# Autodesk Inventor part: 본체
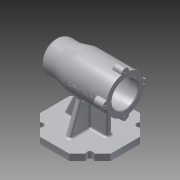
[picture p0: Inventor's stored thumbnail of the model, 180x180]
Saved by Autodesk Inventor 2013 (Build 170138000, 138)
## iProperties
Created: 2019-12
Part Number: 본체
Material: 알루미늄 6061
Document SubType Name: Modeling
Designer: Administrator
Density: 2.71 g/cm^3
Mass: 735.817 g
Surface Area: 721.015 cm^2
Volume: 271.519 cm^3
Author: Administrator
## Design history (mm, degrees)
sketch "스케치1"
  geometry: L1 (-56, 0)-(56, 0); L2 (-56, 0)-(-56, 25); L3 (-56, 25)-(-31, 25); L4 (-31, 25)-(-11, 30); L5 (-11, 30)-(56, 30); L6 (56, 30)-(56, 0); 2 further points
  constraints: 12 end point, 3 perpendicular, 1 coincident, 1 horizontal, 1 midpoint, 1 parallel
  dimensions: "d0" = 25 distance from line of L3.end L2; "d2" = 45 distance from line of L4.end L2; "d3" = 112 distance of L1.start L1.end; "d4" = 50 diameter of L3 L1; "d5" = 60 diameter of L5 L1
revolve "회전1" sketch "스케치1" stored, may be unused: angle "d6" = 90 deg
node "작업 평면1"
sketch "스케치2" dims "d8" = 112
  geometry: L1 (23.196, 56)-(56, 23.196); L2 (56, 23.196)-(56, -23.196); L3 (56, -23.196)-(23.196, -56); L4 (23.196, -56)-(-23.196, -56); L5 (-23.196, -56)-(-56, -23.196); L6 (-56, -23.196)-(-56, 23.196); L7 (-56, 23.196)-(-23.196, 56); L8 (-23.196, 56)-(23.196, 56); 4 further points
  constraints: 16 end point, 2 coincident, 1 horizontal, 1 midpoint, 1 vertical alignment, 19 other
extrude "돌출1" join sketch "스케치2" distance "d9" = 10; taper "d10" = 0 deg
sketch "스케치4"
  geometry: L1 (56, -70)-(56, -80) reference; L2 (56, -80)-(-56, -80) reference; L3 (-56, -80)-(-56, -70) reference; L4 (-56, -70)-(56, -70) reference; L5 (-18.979, -23.234)-(-36, -70); L6 (18.979, -23.234)-(36, -70); L7 (-36, -70)-(36, -70); A1 r 30 centre (0, 0) between (-18.979, -23.234) and (18.979, -23.234) reference; A2 r 30 centre (0, 0) between (-18.979, -23.234) and (18.979, -23.234); A3 r 30 centre (0, 0) between (18.979, -23.234) and (-18.979, -23.234); 1 further point
  constraints: 6 end point, 6 point on circle, 2 centre point, 2 point on line, 1 coincident, 1 collinear, 1 concentric
  dimensions: "d13" = 110 deg angle of L4 L6; "d14" = 110 deg angle of L4 L5; "d15" = 20 distance from line of L5.end L3; "d16" = 20 distance of L1.start L6.end
extrude "돌출2" join sketch "스케치4" stored distance "d17" = 8; taper "d18" = 0 deg
sketch "스케치5"
  geometry: L1 (56, 25)-(56, -25) reference; L2 (56, -25)-(31, -25) reference; L3 (31, -25)-(11, -30) reference; L4 (11, -30)-(4, -30) reference; L5 (4, -30)-(4, -70) reference; L6 (4, -70)-(56, -70) reference; L7 (56, -70)-(56, -80) reference; L8 (56, -80)-(-56, -80) reference; L9 (-56, -80)-(-56, -70) reference; L10 (-56, -70)-(-4, -70) reference; L11 (-4, -70)-(-4, -30) reference; L12 (-4, -30)-(-56, -30) reference; L13 (-56, -30)-(-56, 30) reference; L14 (-56, 30)-(11, 30) reference; L15 (11, 30)-(31, 25) reference; L16 (31, 25)-(56, 25) reference; L17 (38, -70)-(18.476, -28.131); 1 further point
  constraints: 2 end point, 2 point on line
  dimensions: "d19" = 115 deg angle of L17 L6; "d20" = 18 distance from line of L17.start L7
feature "리브1" sketch "스케치5" dims "d21" = 1, "d22" = 8, "d23" = 0, "d24" = 0, "d25" = 1, "d26" = 1
sketch "스케치7"
  geometry: L1 (56, -23.196)-(56, 23.196) reference; L2 (0, 4)-(31, 4); L3 (31, 4)-(31, -4); L4 (31, -4)-(0, -4); L5 (0, -4)-(0, 4); 2 further points
  constraints: 8 end point, 2 parallel, 1 coincident, 1 horizontal, 1 midpoint, 1 perpendicular
  dimensions: "d28" = 8 distance of L2.end L3.end; "d30" = 25 distance between parallel lines of L1 L3
extrude "돌출3" join sketch "스케치7" stored distance "d31" = 8; taper "d32" = 0 deg
sketch "스케치8"
  geometry: L1 (56, 25)-(56, -25) reference; L2 (56, -25)-(31, -25) reference; L3 (31, -25)-(18.476, -28.131) reference; L4 (18.476, -28.131)-(38, -70) reference; L5 (38, -70)-(56, -70) reference; L6 (56, -70)-(56, -80) reference; L7 (56, -80)-(-56, -80) reference; L8 (-56, -80)-(-56, -70) reference; L9 (-56, -70)-(-31, -70) reference; L10 (-31, -70)-(-31, -30) reference; L11 (-31, -30)-(-56, -30) reference; L12 (-56, -30)-(-56, 30) reference; L13 (-56, 30)-(11, 30) reference; L14 (11, 30)-(31, 25) reference; L15 (31, 25)-(56, 25) reference; L16 (50, 0)-(50, 10.5); L17 (50, 10.5)-(47, 10.5); L18 (47, 10.5)-(47, 16); L19 (47, 16)-(43, 16); L20 (43, 16)-(43, 17.5); L21 (43, 17.5)-(25, 17.5); L22 (25, 17.5)-(25, 21); L23 (25, 21)-(13, 21); L24 (13, 21)-(13, 24); L25 (13, 24)-(-41, 24); L26 (-41, 24)-(-41, 21); L27 (-41, 21)-(-56, 21); L28 (-56, 21)-(-56, 0); L29 (50, 0)-(-56, 0); 2 further points
  constraints: 28 end point, 10 parallel, 2 perpendicular, 1 coincident, 1 midpoint, 1 point on line
  dimensions: "d33" = 3 distance of L16.end L17.end; "d35" = 4 distance of L18.end L19.end; "d36" = 18 distance of L20.end L21.end; "d37" = 12 distance of L22.end L23.end; "d38" = 54 distance of L24.end L25.end; "d39" = 15 distance of L26.end L27.end; "d40" = 21 diameter of L17 L29; "d41" = 32 diameter of L19 L29; "d42" = 35 diameter of L21 L29; "d43" = 42 diameter of L23 L29; "d44" = 48 diameter of L25 L29; "d45" = 42 diameter of L27 L29
revolve "회전2" sketch "스케치8" stored, may be unused: angle "d46" = 90 deg
sketch "스케치9"
  geometry: C1 r 21 at (0, 0) reference; C2 r 6 at (0, 30); 1 further point
  constraints: 2 vertical alignment, 1 centre point, 1 other
  dimensions: "d47" = 12 diameter of C2
extrude "돌출4" join sketch "스케치9" distance "d49" = 16; taper "d50" = 0 deg
fillet "모깎기1" dims "d51" = 1
sketch "스케치10"
  geometry: A1 r 6 centre (0, 0) between (5.998, 0.171) and (-5.998, 0.171) reference
hole "구멍1" sketch "스케치10" at (0, 0) diameter "d53" = 3.242; stored, may be unused: countersink angle "d57" = 90 deg, drill point angle "d59" = 118 deg; dims "d54" = 8, "d55" = 4, "d56" = 2, "d58" = 11
sketch "스케치11"
  geometry: L1 (-23.196, 56)-(-56, 23.196) reference; L2 (-23.196, -56)-(23.196, -56) reference; L3 (-62.055, 62.055)-(0, 0); L4 (0, 0)-(-51.254, -51.254); L5 (0, 0)-(-103.787, 0); C1 r 5 at (-39.598, 39.598)
  constraints: 6 end point, 1 centre point, 1 midpoint, 1 parallel, 1 point on line
  dimensions: "d63" = 45 deg angle of L5 L3; "d64" = 45 deg angle of L5 L4; "d65" = 10 diameter of C1
extrude "돌출5" cut sketch "스케치11" stored distance "d66" = 16; taper "d67" = 0 deg
fillet "모깎기3" dims "d71" = 0.3
fillet "모깎기4" dims "d72" = 3
fillet "모깎기6" dims "d74" = 3
fillet "모깎기8" dims "d76" = 3
fillet "모깎기9" dims "d77" = 1
fillet "모깎기10" dims "d78" = 3
chamfer "모따기1" distance "d79" = 1; stored, may be unused: second distance "d80" = 2, angle "d81" = 45 deg
node "작업 평면2"
sketch "스케치12"
  geometry: L1 (56, 6.771)-(56, 29.226) reference; 2 further points
  constraints: 1 horizontal alignment, 1 other
  dimensions: "d83" = 41 distance from line of L1 point (15, 0)
feature "엠보싱1" sketch "스케치12" dims "d84" = 1, "d85" = 0
fillet "모깎기11" dims "d86" = 3, "d87" = 10
node "솔리드1"
pattern_circular "원형 패턴1" dims "d61" = 360 deg
pattern_circular "원형 패턴2" dims angle "d69" = 360 deg
node "절단 모서리 투영2"
node "절단 모서리 투영3"
node "절단 모서리 투영5"
other parameters: "d82" = -77.5
